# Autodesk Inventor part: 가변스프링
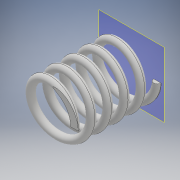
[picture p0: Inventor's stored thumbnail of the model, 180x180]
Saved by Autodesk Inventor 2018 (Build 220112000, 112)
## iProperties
Created: 2019-10
Part Number: 가변스프링
Material: Generic
Document SubType Name: Modeling
Designer: expoc
Density: 1 g/cm^3
Appearance: Default
Author: expoc
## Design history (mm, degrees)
sketch "스케치1"
  geometry: L1 (0, 0)-(21, 0); L2 (21, 0)-(21, 67.25); L3 (21, 67.25)-(0, 67.25); L4 (0, 67.25)-(0, 0); C1 r 3 at (21, 0)
  constraints: 8 end point, 2 parallel, 1 centre point, 1 coincident, 1 horizontal, 1 perpendicular
  dimensions: "d1" = 6 diameter of C1; "d2" = 42 diameter of L2 L4; "d3" = 67.25 distance of L1.end L2.end (derived)
feature "코일1" sketch "스케치1" pitch "d4" = 10; turns "d6" = 5; dims "d5" = 67.25 (= d3), "d7" = 0, angle "d8" = 90 deg, angle "d9" = 90 deg, "d10" = 0, "d11" = 0
sketch "스케치3"
  geometry: L1 (-18, 0)-(-24, 0) reference; 1 further point
  constraints: 1 horizontal alignment
extrude "돌출1" cut sketch "스케치3" extent not by distance; stored distance "d12" = 10; taper "d13" = 0 deg
node "작업 평면1"
sketch "스케치4"
  geometry: L1 (-3, 0)-(3, 0) reference; 1 further point
  constraints: 1 horizontal alignment
extrude "돌출2" cut sketch "스케치4" extent not by distance; stored distance "d15" = 10; taper "d16" = 0 deg
node "솔리드1"
node "절단 모서리 투영1"
node "절단 모서리 투영2"
other parameters: "d14" = 90 deg
